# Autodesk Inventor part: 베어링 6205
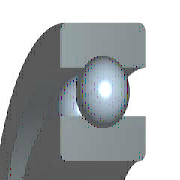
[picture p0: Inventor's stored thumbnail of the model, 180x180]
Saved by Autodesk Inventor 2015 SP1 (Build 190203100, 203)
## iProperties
Company: 한국ATC센터
IsCustomPart: 1
Created: 2009-02
Part Number: 베어링 6205
Material: 강, 연강
Description: 깊은 그루브 볼 베어링
Document SubType Name: Modeling
Standard: KS B 2023
Designer: KYOUNG IL JANG
Standards Organization: KS
Language: ko-KR
Size Designation: 6205 - 25 x 52 x 15
Categories: <MemberInstance><Categories><Category DisplayName="샤프트 부품" InternalName="7f7aeb1f-a693-4053-b835-cee3144e0d98" Mnemonic="SHFT"><Category DisplayName="베어링" Inter
Density: 1 g/cm^3
Appearance: 금속-강
Author: KYOUNG IL JANG
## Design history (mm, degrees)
sketch "스케치" dims "d0" = 7.02 (= -0.26 x WD + 0.26 x BD)
  geometry: L1 (3.99, 19.25)-(11.01, 19.25); L2 (7.5, 19.25)-(7.5, 15.74); L3 (7.5, 19.25)-(7.5, 22.76); L4 (4.892, 16.901)-(0, 16.901); L5 (0, 12.5)-(15, 12.5); L6 (4.892, 21.599)-(0, 21.599); L7 (0, 26)-(15, 26); L8 (15, 12.5)-(15, 16.901); L9 (10.108, 16.901)-(15, 16.901); L10 (10.108, 21.599)-(15, 21.599); L11 (15, 26)-(15, 21.599); L12 (-1.4, 0)-(8.4, 0) reference; L13 (0, -0.3)-(0, 5.3) reference
  constraints: 22 end point, 4 point on line, 2 collinear, 2 perpendicular, 2 symmetric about line, 1 midpoint, 1 parallel, 14 other
  dimensions: "d9" = 25 diameter of L5 L12 (= WD); "d11" = 52 diameter of L7 L12 (= BD); "d12" = 15 distance between parallel lines of L8 L13 (= KB); "d13" = 33.802 diameter of L9 L12 (= 0.326 x BD + 0.674 x WD)
revolve "본체" stored, may be unused: angle "d6" = 90 deg
revolve "볼" stored, may be unused: angle "d7" = 90 deg
pattern_circular "IDS_ARRAYBALL[SIMPL:T]" dims angle "d3" = 360 deg
body "Solid1"
fillet "모깎기1" dims "d1" = 1 (= KRS)
other parameters: "WD" = 25 [user parameter; used in 5 equation terms], "BD" = 52 [user parameter; used in 5 equation terms], "KB" = 15 [user parameter; used in 1 equation term], "KRS" = 1 [user parameter; used in 1 equation term], "d4" = 0, "d5" = 0, "d8" = 0, "d14" = 0, "d15" = 0, "BBA" = 0 [user parameter], "BC0" = 7800000 [user parameter], "BC" = 1.4e+07 [user parameter], "BR" = 26 (= 0.5 x BD) [user parameter], "WR" = 12.5 (= 0.5 x WD) [user parameter]
